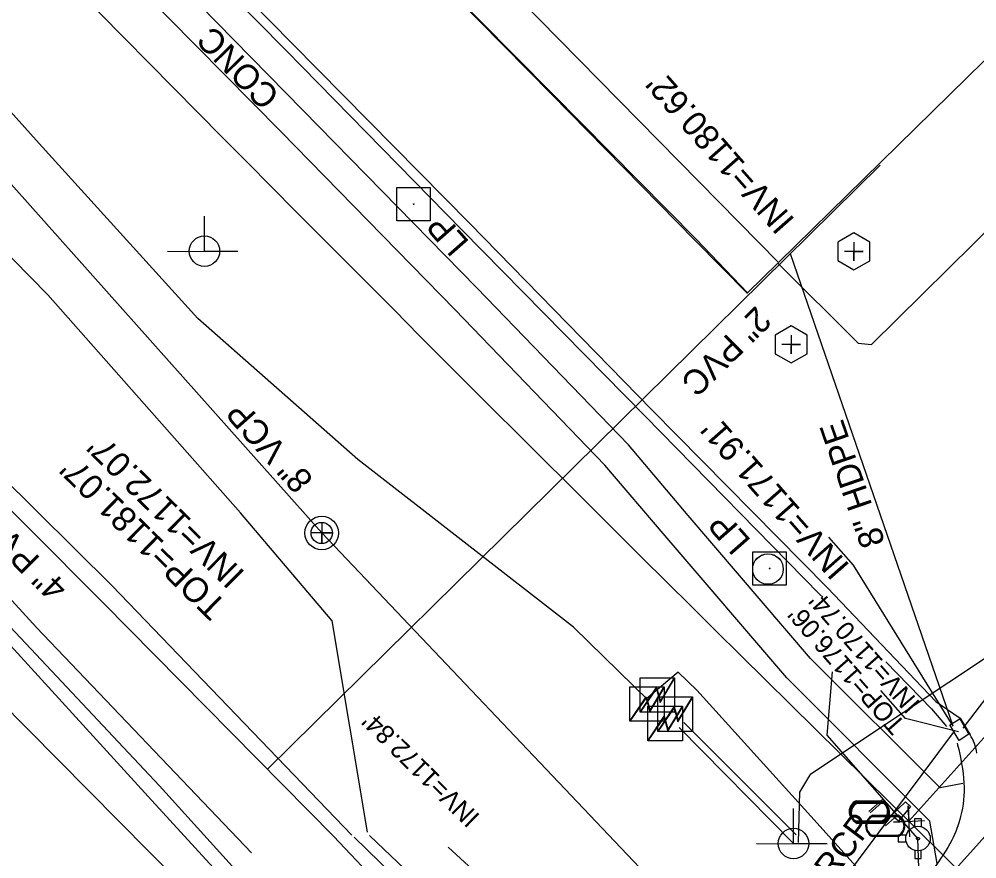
# Model space of a CAD drawing. Extents: x 1263837 to 1268319, y 770628 to 773628.
# Drawn here: x 1267007.9 to 1267162.1, y 771972.7 to 772108 of the extents above; entities that cross this region are included whole.
import ezdxf

# ---------------------------------------------------------------- set-up
doc = ezdxf.new("R2010")
doc.units = 0
for name, color, linetype in [('Exist Building', 7, 'Continuous'), ('Exist Other Culture Area Outline', 7, 'Continuous'), ('Exist Roads EOP Other', 7, 'Continuous'), ('Exist Roads EOP Other Text', 7, 'Continuous'), ('Exist Structure Minor Catch Basin', 7, 'Continuous'), ('Exist Structure Minor Catch Basin Leader', 7, 'Continuous'), ('Exist Structure Minor Catch Basin Top Elevation', 7, 'Continuous'), ('Exist Utilities Gas UG Line SUE LOS B', 7, 'Continuous'), ('Exist Utilities Gas UG Line SUE LOS B Text', 7, 'Continuous'), ('Exist Utilities Other Pole CELL', 7, 'Continuous'), ('Exist Utilities Other Pole With Base CELL', 7, 'Continuous'), ('Exist Utilities Other Pole With Base Text', 7, 'Continuous'), ('Exist Utilities Power Joint Use Telephone CELL', 7, 'Continuous'), ('Exist Utilities Power Transformer CELL', 7, 'Continuous'), ('Exist Utilities Power UG Cable SUE LOS B', 7, 'Continuous'), ('Exist Utilities Telephone UG Cable SUE LOS B', 7, 'Continuous'), ('Exist Utilities Telephone UG FO SUE LOS B', 7, 'Continuous'), ('Exist Utilities Water Fire Hydrant CELL', 7, 'Continuous'), ('Exist Utilities Water Meter CELL', 7, 'Continuous'), ('Exist Utilities Water UG Line SUE LOS B', 7, 'Continuous'), ('Prop Conc Curb 8in x 12in', 7, 'Continuous'), ('Prop Drainage Structure Drop Inlet Grate 2 Narrow Slots and Sag Grates 840 24 CELL', 7, 'Continuous'), ('Prop Drainage Structure Junction Box Convert From Catch Basin Label', 7, 'Continuous'), ('Prop Drainage Structure Junction Box with Manhole Round CELL', 7, 'Continuous'), ('Prop Drainage Structure Pipe RCP 42in Class III Label', 7, 'Continuous'), ('Prop Drainage Structure Pipe RCP 60in Class III', 7, 'Continuous'), ('Prop Drainage Structure Tops and Inverts LABEL', 7, 'Continuous'), ('Prop Earthen Structure Base Ditch Lateral Detail CELL', 7, 'Continuous'), ('Prop Guardrail', 7, 'Continuous'), ('Prop Horizontal Alignment', 7, 'Continuous'), ('Prop Plan Preparation Sketches Hydraulic Ditch', 7, 'Continuous'), ('Prop Retaining Wall', 7, 'Continuous'), ('Prop Shade Heavy', 7, 'Continuous'), ('Prop SS Fill Line', 7, 'Continuous'), ('Prop SS Fill Text', 7, 'Continuous'), ('Prop SS Transition Line', 7, 'Continuous'), ('Prop WCC CELL', 7, 'Continuous'), ('Prop WCR CELL', 7, 'Continuous'), ('Scratch_Level_0', 7, 'Continuous'), ('Scratch_Level_2', 7, 'Continuous'), ('Scratch_Level_5', 7, 'Continuous')]:
    doc.layers.add(name, color=color, linetype=linetype)

# ---------------------------------------------------------------- blocks, each defined once
blk = doc.blocks.new('EXIST UTILITIES SANITARY SEWER MANHOLE')
at = {"layer": 'Prop WCR CELL'}
blk.add_lwpolyline([(0, 0.03425), (0, -0.03425), (0, 0), (0.03425, 0), (-0.03425, 0)], dxfattribs=at)
for radius in [0.05389, 0.03425]:
    blk.add_circle((0, 0), radius, dxfattribs=at)
blk = doc.blocks.new('EXIST UTILITIES SANITARY SEWER CLEAN-OUT')
at = {"layer": 'Prop Conc Curb 8in x 12in'}
blk.add_line((0, 0), (0, 0), dxfattribs=at)
blk.add_lwpolyline([(-0.0516, 0.0299), (-0.0517, -0.0297), (-0.0001, -0.0596), (0.0516, -0.0299), (0.0517, 0.0297), (0.0001, 0.0596)], close=True, dxfattribs=at)
blk.add_lwpolyline([(0, 0.0302), (0, -0.0302), (0, 0), (0.0302, 0), (-0.0302, 0)], dxfattribs=at)
blk = doc.blocks.new('EXIST UTILITIES OTHER POLE')
at = {"layer": 'Exist Utilities Other Pole CELL'}
blk.add_circle((0, 0), 0.0493, dxfattribs=at)
blk = doc.blocks.new('EXIST UTILITIES OTHER POLE WITH BASE')
at = {"layer": 'Exist Utilities Other Pole With Base CELL'}
blk.add_line((0, 0), (0, 0), dxfattribs=at)
blk.add_lwpolyline([(-0.0545, 0.054), (0.0535, 0.054), (0.0535, -0.054), (-0.0545, -0.054), (-0.0545, 0.054)], dxfattribs=at)
blk.add_circle((0, 0), 0.00141, dxfattribs=at)
blk = doc.blocks.new('EXIST UTILITIES POWER JOINT USE TELEPHONE')
at = {"layer": 'Exist Utilities Power Joint Use Telephone CELL'}
blk.add_line((0, 0), (0, 0), dxfattribs=at)
blk.add_lwpolyline([(-0.1188, 0), (0.108, -0.0008), (0, -0.0004), (0, 0.1125)], dxfattribs=at)
blk.add_circle((0, 0.0001), 0.049, dxfattribs=at)
blk = doc.blocks.new('EXIST UTILITIES WATER FIRE HYDRANT')
at = {"layer": 'Exist Utilities Water Fire Hydrant CELL'}
blk.add_line((0, 0), (0, 0), dxfattribs=at)
for points in [[(-0.01025, 0.03825), (-0.01025, 0.064), (0.01025, 0.064), (0.01025, 0.03775)], [(-0.03825, 0.01025), (-0.064, 0.01025), (-0.064, -0.01025), (-0.03825, -0.01025)], [(-0.01025, -0.03825), (-0.01025, -0.064), (0.01025, -0.064), (0.01025, -0.03775)]]:
    blk.add_lwpolyline(points, dxfattribs=at)
for radius in [0.03954, 0.00485]:
    blk.add_circle((0, 0), radius, dxfattribs=at)
blk = doc.blocks.new('EXIST UTILITIES POWER TRANSFORMER')
at = {"layer": 'Exist Utilities Power Transformer CELL'}
blk.add_line((0, 0), (0, 0), dxfattribs=at)
blk.add_lwpolyline([(-0.0569, 0.0522), (0.0542, 0.0522), (0.0542, -0.0588), (-0.0569, -0.0588)], close=True, dxfattribs=at)
for points in [[(-0.0569, -0.0588), (-0.004, 0.0201), (0.0086, -0.0241), (0.0542, 0.0522)], [(-0.0555, -0.0588), (-0.004, 0.0159), (0.0077, -0.0278), (0.0542, 0.0491)]]:
    blk.add_lwpolyline(points, dxfattribs=at)
blk = doc.blocks.new('EXIST UTILITIES WATER METER')
at = {"layer": 'Exist Utilities Water Meter CELL'}
blk.add_line((0, 0), (0, 0), dxfattribs=at)
for points in [[(-0.0408, 0.034), (0.0408, 0.034)], [(-0.0408, 0.0312), (0.0408, 0.0312)], [(0.0408, -0.0312), (-0.0413, -0.0312)], [(0.0408, -0.034), (-0.0413, -0.034)]]:
    blk.add_lwpolyline(points, dxfattribs=at)
for centre, radius, start, end in [((-0.0261, -0.0001), 0.0371, 113.178, 245.9794), ((-0.0259, -0.0001), 0.0347, 115.3009, 243.7824), ((0.0259, 0), 0.0371, 293.6483, 66.3084), ((0.0261, 0), 0.0345, 295.1272, 64.8728)]:
    blk.add_arc(centre, radius, start, end, dxfattribs=at)

msp = doc.modelspace()

# ---------------------------------------------------------------- linework, layer by layer
at = {"layer": 'Exist Building'}
msp.add_lwpolyline([(1267094.21, 772243.81), (1267034, 772184.58), (1267033.81, 772166.88), (1267130.22, 772068.76), (1267199.08, 772136.41), (1267094.21, 772243.81)], dxfattribs=at)
at = {"layer": 'Exist Other Culture Area Outline'}
msp.add_lwpolyline([(1267150.65, 771981.85), (1267151.47, 771981.11), (1267149.5, 771978.76), (1267148.39, 771979.71), (1267150.65, 771981.85)], dxfattribs=at)
at = {"layer": 'Exist Roads EOP Other'}
for points in [[(1267045.35, 772145.37), (1267070.23, 772119.83), (1267093.74, 772096.02), (1267116.95, 772072.53), (1267125.22, 772063.89), (1267130.09, 772068.65), (1267143.03, 772055.76), (1267145.17, 772055.59), (1267165.74, 772075.85)], [(1267159.91, 771984.79), (1267156.22, 771984.11), (1267135.35, 772004.96), (1267115.66, 772028), (1267106.02, 772039.39), (1267081.61, 772064.71), (1267053.59, 772093.35), (1267031.43, 772116), (1267019.15, 772128.52)], [(1267155.77, 771971.93), (1267154.55, 771978.76), (1267131.51, 772001.83), (1267111.96, 772024.71), (1267102.24, 772036.12), (1267078.14, 772061.16), (1267050.03, 772089.91), (1267027.35, 772112.96), (1267015.53, 772125.08)]]:
    msp.add_lwpolyline(points, dxfattribs=at)
at = {"layer": 'Exist Structure Minor Catch Basin'}
msp.add_lwpolyline([(1267157.78, 771994.26), (1267159.4, 771995.24), (1267160.86, 771992.76), (1267159.32, 771991.76), (1267157.78, 771994.26)], dxfattribs=at)
at = {"layer": 'Exist Structure Minor Catch Basin Leader'}
msp.add_lwpolyline([(1267159.2, 771993.15), (1267150.65, 771995.31), (1267146.68, 771999.81)], dxfattribs=at)
at = {"layer": 'Exist Utilities Gas UG Line SUE LOS B'}
msp.add_line((1267047.89, 771987.11), (1267146.57, 772084.47), dxfattribs=at)
msp.add_lwpolyline([(1267251.66, 771778.25), (1267245.66, 771783.24), (1267207.76, 771821.81), (1267173.99, 771856.22), (1267107.23, 771924.68), (1267058.55, 771976.3), (1267021.45, 772013.9), (1266984.81, 772050.66), (1266941.85, 772095.07), (1266910.9, 772129.48), (1266882, 772160.62)], dxfattribs=at)
at = {"layer": 'Exist Utilities Power UG Cable SUE LOS B'}
msp.add_line((1267114.97, 771994.66), (1267133.05, 771976.52), dxfattribs=at)
msp.add_lwpolyline([(1267133.44, 771975.32), (1267133.62, 771983.44), (1267135.4, 771986.37), (1267187.38, 772020.93), (1267199.07, 772032.56)], dxfattribs=at)
at = {"layer": 'Exist Utilities Telephone UG Cable SUE LOS B'}
msp.add_line((1267114.19, 771993.82), (1267132.61, 771975.12), dxfattribs=at)
for points in [[(1267045.29, 771973.62), (1267010.7, 772009.94), (1266980.19, 772043.3), (1266936.41, 772092.71), (1266907.08, 772125.97), (1266885.75, 772164.56), (1266881.04, 772182.11), (1266893.51, 772207.84), (1266893.04, 772220.24)], [(1267061.48, 771976.49), (1267022.89, 772016.68), (1266986.48, 772052.73), (1266949.35, 772096.59), (1266916.72, 772138.28), (1266892.38, 772169.77), (1266884.02, 772182.49), (1266894.19, 772207.62), (1266893.04, 772220.24)], [(1267392.03, 771642.05), (1267309.91, 771722.47), (1267265.68, 771767.66), (1267210.14, 771824.35), (1267175.87, 771860.6), (1267111.82, 771927.45), (1267061.85, 771976.15)]]:
    msp.add_lwpolyline(points, dxfattribs=at)
at = {"layer": 'Exist Utilities Telephone UG FO SUE LOS B'}
for points in [[(1267063.99, 771976.99), (1267058.29, 772011.02), (1267043.56, 772028.46), (1267012.53, 772063.58), (1266981.88, 772094.72), (1266952.85, 772129.68), (1266918.67, 772160.32), (1266892.22, 772194.04), (1266869.77, 772217.7), (1266827.84, 772258.92), (1266816.85, 772269.34), (1266796.74, 772289.13)], [(1267109.33, 771998.14), (1267097.15, 772009.99), (1267062.43, 772037.02), (1267036.69, 772059.77), (1267011.11, 772087.97), (1266968.47, 772135.55), (1266950.56, 772163.04), (1266928.64, 772189.36), (1266913.94, 772213.45), (1266904.16, 772218.55)], [(1267402.3, 771719.43), (1267352.82, 771769), (1267334.68, 771788.64), (1267283.58, 771836.93), (1267255.34, 771868.58), (1267217.3, 771901.29), (1267146.08, 771967.68), (1267135.38, 771979.55), (1267117.02, 771999.86), (1267114.01, 772002.75), (1267108.97, 771998.49)], [(1268035.78, 770997.15), (1267940.84, 771107.94), (1267897.35, 771156.24), (1267867.85, 771183.87), (1267810.07, 771229.4), (1267770.21, 771268.8), (1267721.65, 771316.15), (1267671.88, 771358.99), (1267623.8, 771405.23), (1267607.14, 771420.63), (1267574.79, 771453.25), (1267517.7, 771508.8), (1267479.52, 771551.33), (1267465.41, 771567.06), (1267416.72, 771620.51), (1267391.64, 771647.4), (1267311.09, 771724.38), (1267266.64, 771768.8), (1267249.06, 771785.93), (1267211.37, 771825.47), (1267176.84, 771861.92), (1267114.4, 771928.7), (1267064.3, 771976.43)]]:
    msp.add_lwpolyline(points, dxfattribs=at)
at = {"layer": 'Exist Utilities Water UG Line SUE LOS B'}
for p, q in [((1267147.03, 771982.34), (1267144.74, 771980.32)), ((1267147.24, 771982.11), (1267144.94, 771980.09)), ((1267149.35, 771979.7), (1267147.41, 771978)), ((1267076.99, 771974.56), (1267116.38, 771938.65))]:
    msp.add_line(p, q, dxfattribs=at)
for points in [[(1267152.66, 771975.95), (1267138.01, 771992.6), (1267138.9, 772002.81)], [(1267168.62, 771849.04), (1267191.96, 771874.07), (1267183.71, 771925.32), (1267152.83, 771969.69), (1267152.66, 771975.95)]]:
    msp.add_lwpolyline(points, dxfattribs=at)
at = {"layer": 'Prop Drainage Structure Pipe RCP 42in Class III Label'}
msp.add_line((1267158.31, 771994.05), (1267132.1, 772070.19), dxfattribs=at)
at = {"layer": 'Prop Drainage Structure Pipe RCP 60in Class III'}
msp.add_line((1267151.2, 771978.73), (1267151.2, 771978.73), dxfattribs=at)
msp.add_lwpolyline([(1267151.34, 771976.24), (1267151.06, 771981.23), (1267151.2, 771978.73), (1267148.7, 771978.6), (1267153.69, 771978.87)], dxfattribs=at)
at = {"layer": 'Prop Guardrail'}
msp.add_line((1267287.51, 772131.04), (1267151.2, 771978.73), dxfattribs=at)
at = {"layer": 'Prop Horizontal Alignment'}
for p in [(1268113.05, 771031.32), (1267144.12, 771985.71)]:
    msp.add_line(p, (1267144.12, 771985.71), dxfattribs=at)
msp.add_arc((1275094.23, 780056.99), 11329.16, 223.613619, 225.433333, dxfattribs=at)
at = {"layer": 'Prop Plan Preparation Sketches Hydraulic Ditch'}
msp.add_lwpolyline([(1267158.31, 771994.05), (1267142.25, 772019.98), (1267138.29, 772024.49)], dxfattribs=at)
at = {"layer": 'Prop Shade Heavy'}
msp.add_line((1267158.35, 771993.02), (1267117.4, 771938.33), dxfattribs=at)
at = {"layer": 'Prop SS Fill Line'}
msp.add_line((1267158.96, 771991.32), (1267159.05, 771991.06), dxfattribs=at)
for points in [[(1267022.26, 772131.94), (1267050.92, 772102.94), (1267079.25, 772073.97), (1267108.64, 772044.08), (1267136.87, 772015.29), (1267137.33, 772014.82)], [(1267147.46, 772004.42), (1267154.83, 771996.85), (1267157.27, 771994)]]:
    msp.add_lwpolyline(points, dxfattribs=at)
msp.add_spline([(1267159.05, 771991.06), (1267160.06, 771984.89), (1267159.53, 771979.48), (1267158.11, 771975.68), (1267155.19, 771971.1)], degree=3, dxfattribs=at)
at = {"layer": 'Prop SS Fill Text'}
for points in [[(1267045.25, 772145.18), (1267070.26, 772119.68), (1267093.66, 772095.88), (1267116.76, 772072.32), (1267125.21, 772063.79)], [(1266893.21, 772133.72), (1266919.52, 772104.22), (1266948.24, 772073.49), (1266976.6, 772042.43), (1267003.89, 772012.69), (1267030.51, 771984.42), (1267055.98, 771956.23), (1267082.18, 771926.96)], [(1267023.36, 772133.07), (1267051.93, 772104.05), (1267080.48, 772075.07), (1267109.8, 772045.02), (1267138.08, 772016.35), (1267155.56, 771998.02), (1267159.46, 771995.33), (1267161.04, 771992.68)], [(1267213.05, 772032.03), (1267189.78, 772005.9), (1267176.3, 771990.61), (1267155.85, 771967.82), (1267138.24, 771948.5), (1267125.42, 771934.43), (1267121.06, 771929.94), (1267119.7, 771931.05), (1267117.27, 771928.82), (1267108.72, 771923.59)]]:
    msp.add_lwpolyline(points, dxfattribs=at)
msp.add_ellipse((1267155, 771988.63), major_axis=(-1.61, 7.47), ratio=0.945629, start_param=4.655678, end_param=5.072095, dxfattribs=at)
at = {"layer": 'Prop SS Transition Line'}
for points in [[(1266852.05, 772155.61), (1266878.43, 772128.6), (1266907.35, 772098.32), (1266935.74, 772069.18), (1266969.41, 772034.22), (1266999.55, 772003.34), (1267028.81, 771973.8), (1267057.41, 771945.22), (1267085.34, 771917.2), (1267106.93, 771895.42)], [(1266892.05, 772132.4), (1266918.74, 772103.45), (1266946.95, 772072.12), (1266975.02, 772041.09), (1267002.55, 772011.32), (1267028.69, 771982.73), (1267054.25, 771954.75), (1267080.46, 771925.43), (1267105.81, 771897.39), (1267132.71, 771869.91), (1267147, 771855.87), (1267172.96, 771830.15)]]:
    msp.add_lwpolyline(points, dxfattribs=at)
at = {"layer": 'Prop WCC CELL'}
msp.add_line((1267271.52, 772140.75), (1267159.9, 771993.71), dxfattribs=at)
at = {"layer": 'Scratch_Level_2'}
msp.add_arc((1275094.23, 780056.99), 11459.16, 216.983333, 225.433333, dxfattribs=at)
at = {"layer": 'Scratch_Level_5'}
for p in [(1266888.65, 772213.85), (1267168.26, 771907.7)]:
    msp.add_line(p, (1267056.62, 772025.19), dxfattribs=at)

# ---------------------------------------------------------------- block references
at = {"layer": 'Exist Utilities Other Pole CELL', "xscale": 50, "yscale": 50}
for p in [(1267128.5, 772019.38), (1267128.5, 772019.36)]:
    msp.add_blockref('EXIST UTILITIES OTHER POLE', p, dxfattribs=at)
at = {"layer": 'Exist Utilities Other Pole With Base CELL', "xscale": 50, "yscale": 50}
for p in [(1267071.43, 772078.19), (1267128.77, 772019.47)]:
    msp.add_blockref('EXIST UTILITIES OTHER POLE WITH BASE', p, dxfattribs=at)
at = {"layer": 'Exist Utilities Power Joint Use Telephone CELL', "xscale": 50, "yscale": 50}
for p in [(1267037.73, 772070.61), (1267132.61, 771975.14)]:
    msp.add_blockref('EXIST UTILITIES POWER JOINT USE TELEPHONE', p, dxfattribs=at)
at = {"layer": 'Exist Utilities Power Transformer CELL', "xscale": 50, "yscale": 50}
for p in [(1267110.75, 771999.26), (1267109.09, 771997.78), (1267113.61, 771996.16), (1267112, 771994.65)]:
    msp.add_blockref('EXIST UTILITIES POWER TRANSFORMER', p, dxfattribs=at)
at = {"layer": 'Exist Utilities Water Fire Hydrant CELL', "xscale": 50, "yscale": 50}
msp.add_blockref('EXIST UTILITIES WATER FIRE HYDRANT', (1267152.66, 771975.95), dxfattribs=at)
at = {"layer": 'Exist Utilities Water Meter CELL', "xscale": 50, "yscale": 50}
for p in [(1267144.74, 771980.32), (1267144.94, 771980.09), (1267147.38, 771977.96), (1267147.41, 771978)]:
    msp.add_blockref('EXIST UTILITIES WATER METER', p, dxfattribs=at)
at = {"layer": 'Prop Conc Curb 8in x 12in', "xscale": 50, "yscale": 50}
for p in [(1267142.34, 772070.57), (1267132.23, 772055.57)]:
    msp.add_blockref('EXIST UTILITIES SANITARY SEWER CLEAN-OUT', p, dxfattribs=at)
at = {"layer": 'Prop WCR CELL', "xscale": 50, "yscale": 50}
msp.add_blockref('EXIST UTILITIES SANITARY SEWER MANHOLE', (1267056.62, 772025.19), dxfattribs=at)

# ---------------------------------------------------------------- texts
at = {"layer": 'Exist Roads EOP Other Text'}
msp.add_text('CONC', height=4, rotation=134.3825, dxfattribs=at).set_placement((1267050.07, 772095.87))
at = {"layer": 'Exist Structure Minor Catch Basin Top Elevation'}
msp.add_text("TOP=1176.06'", height=3, rotation=131.3556, dxfattribs=at).set_placement((1267150.82, 771994.42))
at = {"layer": 'Exist Utilities Gas UG Line SUE LOS B Text'}
for s, rotation, p in [('2" PVC', 224.618, (1267126.59, 772061.95)), ('4" PVC', 134.9079, (1267015.94, 772016.6))]:
    msp.add_text(s, height=4, rotation=rotation, dxfattribs=at).set_placement(p)
at = {"layer": 'Exist Utilities Other Pole With Base Text'}
for p in [(1267080.53, 772072.07), (1267125.89, 772023.97)]:
    msp.add_text('LP', height=4, rotation=131.3556, dxfattribs=at).set_placement(p)
at = {"layer": 'Prop Drainage Structure Drop Inlet Grate 2 Narrow Slots and Sag Grates 840 24 CELL'}
msp.add_text("INV=1172.84'", height=3, rotation=135.4333, dxfattribs=at).set_placement((1267082.27, 771979.61))
at = {"layer": 'Prop Drainage Structure Junction Box Convert From Catch Basin Label'}
msp.add_text("INV=1170.74'", height=3, rotation=131.3556, dxfattribs=at).set_placement((1267153.17, 771997.78))
at = {"layer": 'Prop Drainage Structure Junction Box with Manhole Round CELL'}
msp.add_text('8" HDPE', height=4, rotation=108.9972, dxfattribs=at).set_placement((1267147.41, 772023.64))
at = {"layer": 'Prop Drainage Structure Tops and Inverts LABEL'}
msp.add_text('18" RCP', height=4, rotation=53.1766, dxfattribs=at).set_placement((1267133.26, 771961.57))
at = {"layer": 'Prop Earthen Structure Base Ditch Lateral Detail CELL'}
for s, p in [("INV=1180.62'", (1267132.98, 772075.64)), ("INV=1171.91'", (1267141.83, 772019.93))]:
    msp.add_text(s, height=4, rotation=131.3556, dxfattribs=at).set_placement(p)
at = {"layer": 'Prop Retaining Wall'}
for s, p in [("INV=1172.07'", (1267044.41, 772018.78)), ("TOP=1181.07'", (1267041.51, 772013.73))]:
    msp.add_text(s, height=4, rotation=135.4634, dxfattribs=at).set_placement(p)
at = {"layer": 'Scratch_Level_0'}
msp.add_text('8" VCP', height=4, rotation=131.681, dxfattribs=at).set_placement((1267055.45, 772033.89))

doc.saveas('drawing.dxf')
